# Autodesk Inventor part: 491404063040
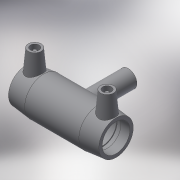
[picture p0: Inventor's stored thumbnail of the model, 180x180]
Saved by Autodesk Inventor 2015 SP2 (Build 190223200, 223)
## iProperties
Created: 2017-06
Part Number: 491404063040
Material: Generic
Description: PLASSON REDUCING TEE 63x40x63
Document SubType Name: Modeling
Designer: KIM
Mass: 57.3761 g
Surface Area: 241.06 cm^2
Volume: 57.3761 cm^3
Density: 1 g/cm^3
Appearance: Default
Author: KIM
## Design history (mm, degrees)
derived "491404.ipt"
feature "Solid1::491404.ipt"
tag "TaggingFeature1"
body "Solid1"
other parameters: "d0" = 167, "d1" = 63, "d2" = 82, "d3" = 58, "d4" = 33.4, "d5" = 73.8, "d6" = 59.85, "d7" = 63, "d8" = 168 deg, "d10" = 23.2, "d11" = 7.73333, "d13" = 167, "d14" = 17.6296, "d17" = 56.7, "d18" = 63, "d19" = 3.52592, "d20" = 168 deg, "d22" = 76.26, "d23" = 82, "d25" = 135 deg, "d26" = 116.9, "d29" = 58, "d30" = 15, "d31" = 66.8, "d34" = 5 deg, "d35" = 15, "d39" = 5 deg, "d41" = 4, "d42" = 14, "d43" = 0, "d45" = 4, "d46" = 6, "d47" = 0, "d48" = -104, "d51" = 0, "d52" = 32, "d54" = 0, "d55" = 73.8, "d56" = 82, "d57" = 58.45, "d58" = 135 deg, "d59" = 58, "d60" = 58, "d61" = 135 deg, "d62" = 104, "d72" = 75.985, "d73" = 37.9925, "d74" = -104, "d75" = 42, "d77" = 0, "d78" = 32, "d80" = 0, "d82" = 63, "d83" = 0, "d84" = 3, "d85" = 0, "d86" = 19.33333, "d87" = 74.7348, "d88" = 7.73333, "d89" = 3, "d90" = 0, "d_" = 63, "L_" = 167, "L_1" = 58, "D_" = 82, "A_" = 58, "d_2" = 12, "H_" = 104
